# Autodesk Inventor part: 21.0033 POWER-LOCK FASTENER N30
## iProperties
Created: 2012-10
Part Number: 21.0033 POWER-LOCK FASTENER N30
Document SubType Name: Modeling
Designer: Administrator
Density: 7.85 g/cm^3
Material: Steel
Mass: 17.5542 g
Surface Area: 16.3453 cm^2
Volume: 2.2362 cm^3
Author: Administrator
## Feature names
1. Base1
